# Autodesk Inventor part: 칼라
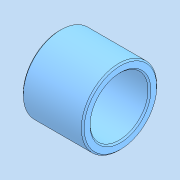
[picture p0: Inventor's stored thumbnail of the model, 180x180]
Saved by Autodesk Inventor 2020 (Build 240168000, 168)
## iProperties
Created: 2025-01
Part Number: 칼라
Material: 강철, 연강
Document SubType Name: Modeling
Designer: 1강의실14
Density: 7.85 g/cm^3
Appearance: 기본값
Author: jhkim
Sending System: Autodesk Inventor 2025
Preprocessor: ST-DEVELOPER v20
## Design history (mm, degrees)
feature "솔리드1"
node "솔리드2"
